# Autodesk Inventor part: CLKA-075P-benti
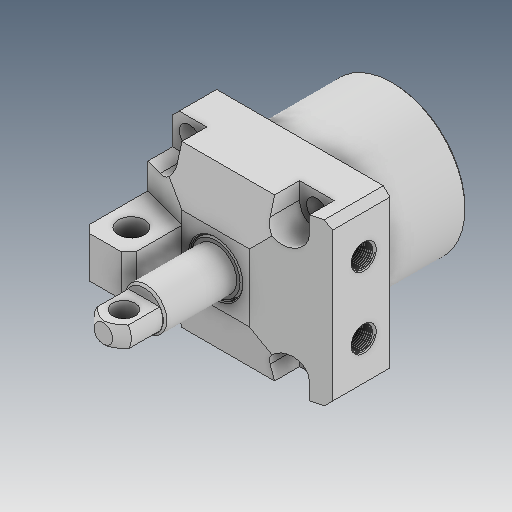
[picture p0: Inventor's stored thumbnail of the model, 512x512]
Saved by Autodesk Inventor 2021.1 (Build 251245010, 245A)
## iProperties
Created: 2018-07
Part Number: CLKA-075P-benti
Material: Ogólny
Document SubType Name: Modeling
Designer: user
Density: 1 g/cm^3
Appearance: Domyślna
Author: user
Revision Number: ÈÎºÎ
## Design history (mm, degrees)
feature "Í¹Ì¨-À­Éì5"
node "Bryła1"
